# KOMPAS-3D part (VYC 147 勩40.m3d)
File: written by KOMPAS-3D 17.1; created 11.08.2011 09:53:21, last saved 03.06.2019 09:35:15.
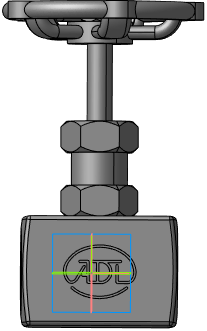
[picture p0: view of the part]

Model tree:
1. Плоскость XY
2. Плоскость ZX
3. Плоскость ZY
4. Ось X
5. Ось Y
6. Ось Z
7. Начало координат
8. Операция без истории:2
